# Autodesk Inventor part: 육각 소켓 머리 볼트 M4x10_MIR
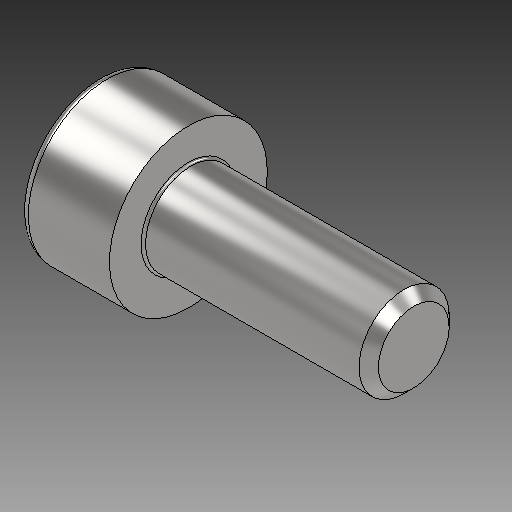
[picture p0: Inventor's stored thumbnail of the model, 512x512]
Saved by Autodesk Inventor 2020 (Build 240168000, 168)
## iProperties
Created: 2024-08
Part Number: 육각 소켓 머리 볼트 M4x10_MIR
Material: 강철, 연강
Description: 6각머리 태핑 나사
Document SubType Name: Modeling
Designer: 1강의실14
Density: 7.85 g/cm^3
Appearance: 기본값
Author: jhkim
Sending System: Autodesk Inventor 2025
Preprocessor: ST-DEVELOPER v20
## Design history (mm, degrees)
derived "육각 소켓 머리 볼트 M4x10.ipt"
feature "솔리드1::육각 소켓 머리 볼트 M4x10.ipt" dims "d0" = 10
tag "피쳐 태그1"
node "솔리드1"
